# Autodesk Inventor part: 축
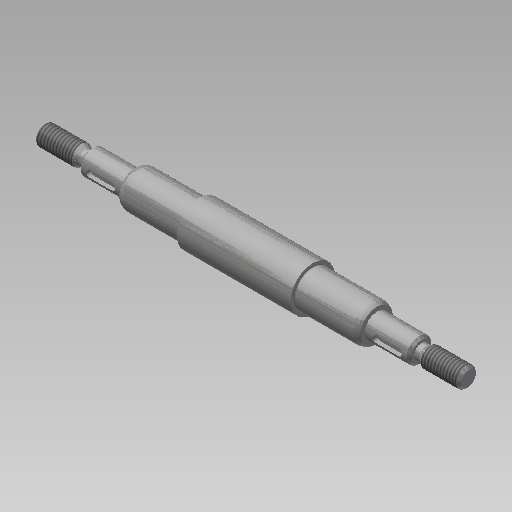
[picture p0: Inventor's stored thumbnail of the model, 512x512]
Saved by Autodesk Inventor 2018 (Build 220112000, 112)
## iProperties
Created: 2015-11
Part Number: 축
Material: 강철, 연강
Document SubType Name: Modeling
Designer: mduedu
Density: 7.86 g/cm^3
Mass: 198.507 g
Surface Area: 75.8873 cm^2
Volume: 25.2553 cm^3
Appearance: 강철
Author: mduedu
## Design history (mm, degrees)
sketch "스케치1"
  geometry: L1 (-86, 0)-(86, 0); L2 (-86, 0)-(-86, 4); L3 (-86, 4)-(-70.732, 4); L4 (-70.732, 4)-(-69, 3); L5 (-69, 3)-(-67, 3); L6 (-67, 3)-(-67, 5); L7 (-67, 5)-(-49, 5); L8 (-49, 5)-(-49, 6.55); L9 (-47.355, 7.5)-(-23, 7.5); L10 (-23, 7.5)-(-23, 9); L11 (0, 0)-(0, 9); L12 (86, 4)-(70.732, 4); L13 (70.732, 4)-(69, 3); L14 (69, 3)-(67, 3); L15 (67, 3)-(67, 5); L16 (67, 5)-(49, 5); L17 (23, 7.5)-(23, 9); L18 (86, 0)-(86, 4); L19 (-23, 9)-(23, 9); L20 (-49, 6.55)-(-47.355, 7.5); L21 (47.355, 7.5)-(23, 7.5); L22 (49, 6.55)-(47.355, 7.5); L23 (49, 5)-(49, 6.55); 1 further point
  constraints: 46 end point, 10 symmetric about line, 6 perpendicular, 5 parallel, 2 midpoint, 1 coincident, 1 horizontal
  dimensions: "d0" = 172 distance of L1.start L1.end (derived); "d1" = 8 diameter of L3 L1; "d2" = 30 deg angle of L4 L5; "d3" = 6 diameter of L5 L1; "d4" = 10 diameter of L7 L1; "d5" = 15 diameter of L9 L1; "d6" = 18 diameter of L19 L1; "d8" = 18 distance of L6.end L7.end; "d9" = 46 distance of L10.end L17.end; "d10" = 2 distance of L4.end L5.end; "d11" = 17 distance from line of L4.end L2; "d16" = 13.1 diameter of L8.end L1; "d17" = 30 deg angle of L20 L9; "d18" = 26 distance between parallel lines of L10 L8
revolve "회전1" sketch "스케치1" stored, may be unused: angle "d12" = 90 deg
chamfer "모따기1" distance "d13" = 1; stored, may be unused: second distance "d14" = 2, angle "d15" = 45 deg
fillet "모깎기1" dims "d19" = 4, "d20" = 0.5
node "작업 평면1"
sketch "스케치2" dims "d23" = 12
  geometry: L1 (-4.5, 1.5)-(4.5, 1.5); L2 (4.5, 1.5)-(4.5, -1.5); L3 (4.5, -1.5)-(-4.5, -1.5); L4 (-4.5, -1.5)-(-4.5, 1.5); L5 (-9, -4)-(-9, 4) reference; 3 further points
  constraints: 8 end point, 2 midpoint, 2 parallel, 2 vertical alignment, 1 horizontal, 1 perpendicular, 4 other
  dimensions: "d21" = 3 distance between parallel lines of L3 L1; "d24" = 3 dimension on L5
extrude "돌출1" cut sketch "스케치2" distance "d25" = 1.8; taper "d26" = 0 deg
feature "스레드1" dims "d27" = 10, "d28" = 0
feature "스레드2" dims "d29" = 10, "d30" = 0
chamfer "모따기2" distance "d31" = 1; stored, may be unused: second distance "d32" = 2, angle "d33" = 45 deg
fillet "모깎기2" dims "d34" = 0.3
node "솔리드1"
mirror "대칭1"
